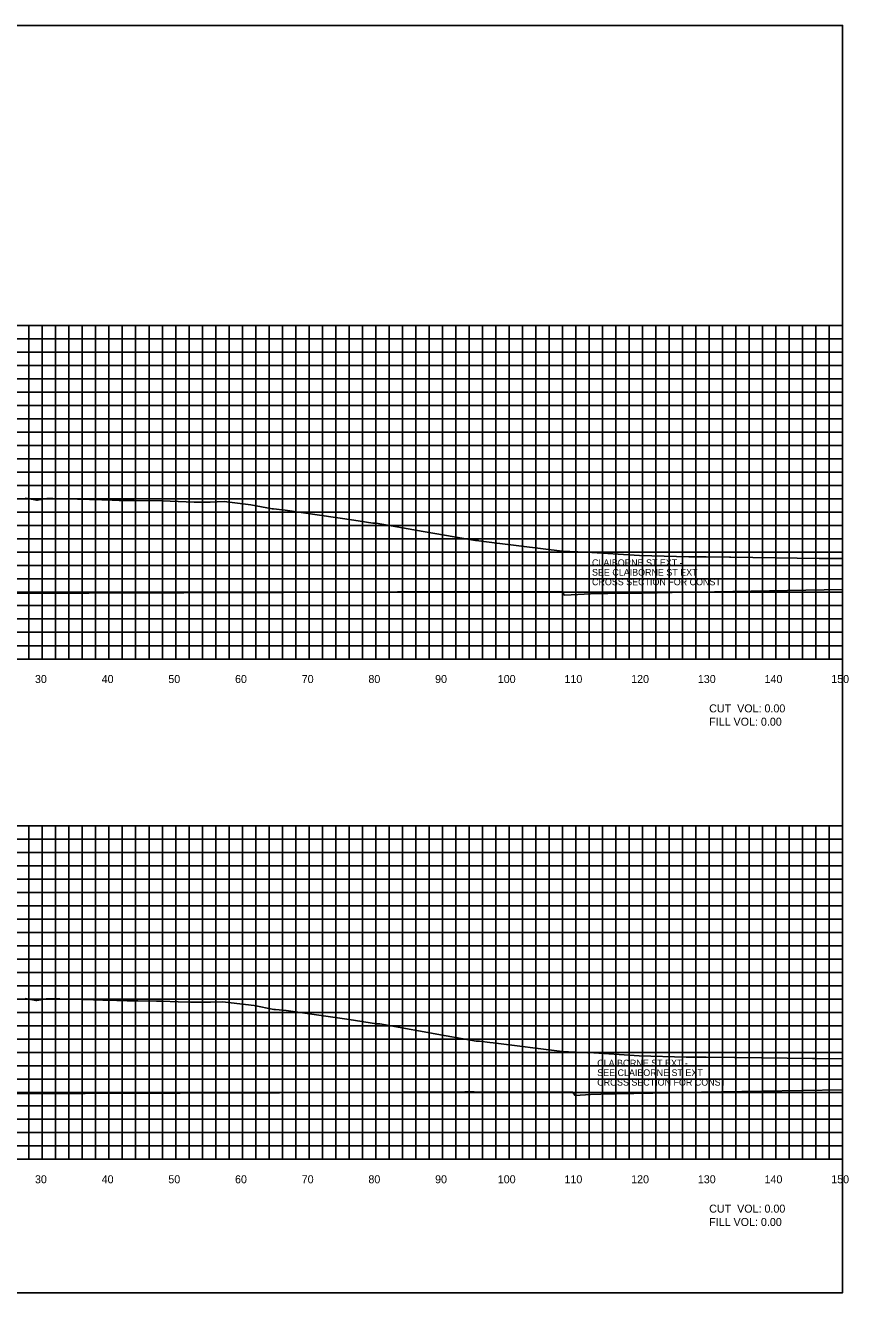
# Model space of a CAD drawing. Extents: x 1797305 to 1804485, y 245831 to 250849.
# Drawn here: x 1804018.5 to 1804141.9, y 250079.4 to 250269.4 of the extents above; entities that cross this region are included whole.
import ezdxf

# ---------------------------------------------------------------- set-up
doc = ezdxf.new("R2010")
doc.units = 0
for name, color, linetype in [('10', 7, 'Continuous'), ('29', 7, 'Continuous'), ('CL-CNST', 7, 'Continuous'), ('EDPV-LINE', 7, 'Continuous'), ('Level 31', 7, 'Continuous'), ('LIMT-CSLINE', 7, 'Continuous'), ('M-ROADS', 7, 'Continuous')]:
    doc.layers.add(name, color=color, linetype=linetype)

msp = doc.modelspace()

# ---------------------------------------------------------------- linework, layer by layer
msp.add_lwpolyline([(1803841, 250079.43), (1804141, 250079.43), (1804141, 250269.43), (1803841, 250269.43)], close=True)
at = {"layer": '29'}
for p, q in [((1803841, 250224.43), (1804141, 250224.43)), ((1804019, 250174.43), (1804019, 250224.43)), ((1804021, 250174.43), (1804021, 250224.43)), ((1804023, 250174.43), (1804023, 250224.43)), ((1804025, 250174.43), (1804025, 250224.43)), ((1804027, 250174.43), (1804027, 250224.43)), ((1804029, 250174.43), (1804029, 250224.43)), ((1804031, 250174.43), (1804031, 250224.43)), ((1804033, 250174.43), (1804033, 250224.43)), ((1804035, 250174.43), (1804035, 250224.43)), ((1804037, 250174.43), (1804037, 250224.43)), ((1804039, 250174.43), (1804039, 250224.43)), ((1804041, 250174.43), (1804041, 250224.43)), ((1804043, 250174.43), (1804043, 250224.43)), ((1804045, 250174.43), (1804045, 250224.43)), ((1804047, 250174.43), (1804047, 250224.43)), ((1804049, 250174.43), (1804049, 250224.43)), ((1804051, 250174.43), (1804051, 250224.43)), ((1804053, 250174.43), (1804053, 250224.43)), ((1804055, 250174.43), (1804055, 250224.43)), ((1804057, 250174.43), (1804057, 250224.43)), ((1804059, 250174.43), (1804059, 250224.43)), ((1804061, 250174.43), (1804061, 250224.43)), ((1804063, 250174.43), (1804063, 250224.43)), ((1804065, 250174.43), (1804065, 250224.43)), ((1804067, 250174.43), (1804067, 250224.43)), ((1804069, 250174.43), (1804069, 250224.43)), ((1804071, 250174.43), (1804071, 250224.43)), ((1804073, 250174.43), (1804073, 250224.43)), ((1804075, 250174.43), (1804075, 250224.43)), ((1804077, 250174.43), (1804077, 250224.43)), ((1804079, 250174.43), (1804079, 250224.43)), ((1804081, 250174.43), (1804081, 250224.43)), ((1804083, 250174.43), (1804083, 250224.43)), ((1804085, 250174.43), (1804085, 250224.43)), ((1804087, 250174.43), (1804087, 250224.43)), ((1804089, 250174.43), (1804089, 250224.43)), ((1804091, 250174.43), (1804091, 250224.43)), ((1804093, 250174.43), (1804093, 250224.43)), ((1804095, 250174.43), (1804095, 250224.43)), ((1804097, 250174.43), (1804097, 250224.43)), ((1804099, 250174.43), (1804099, 250224.43)), ((1804101, 250174.43), (1804101, 250224.43)), ((1804103, 250174.43), (1804103, 250224.43)), ((1804105, 250174.43), (1804105, 250224.43)), ((1804107, 250174.43), (1804107, 250224.43)), ((1804109, 250174.43), (1804109, 250224.43)), ((1804111, 250174.43), (1804111, 250224.43)), ((1804113, 250174.43), (1804113, 250224.43)), ((1804115, 250174.43), (1804115, 250224.43)), ((1804117, 250174.43), (1804117, 250224.43)), ((1804119, 250174.43), (1804119, 250224.43)), ((1804121, 250174.43), (1804121, 250224.43)), ((1804123, 250174.43), (1804123, 250224.43)), ((1804125, 250174.43), (1804125, 250224.43)), ((1804127, 250174.43), (1804127, 250224.43)), ((1804129, 250174.43), (1804129, 250224.43)), ((1804131, 250174.43), (1804131, 250224.43)), ((1804133, 250174.43), (1804133, 250224.43)), ((1804135, 250174.43), (1804135, 250224.43)), ((1804137, 250174.43), (1804137, 250224.43)), ((1804139, 250174.43), (1804139, 250224.43)), ((1804141, 250174.43), (1804141, 250224.43)), ((1803841, 250222.43), (1804141, 250222.43)), ((1803841, 250220.43), (1804141, 250220.43)), ((1803841, 250218.43), (1804141, 250218.43)), ((1803841, 250216.43), (1804141, 250216.43)), ((1803841, 250214.43), (1804141, 250214.43)), ((1803841, 250212.43), (1804141, 250212.43)), ((1803841, 250210.43), (1804141, 250210.43)), ((1803841, 250208.43), (1804141, 250208.43)), ((1803841, 250206.43), (1804141, 250206.43)), ((1803841, 250204.43), (1804141, 250204.43)), ((1803841, 250202.43), (1804141, 250202.43)), ((1803841, 250200.43), (1804141, 250200.43)), ((1803841, 250198.43), (1804141, 250198.43)), ((1803841, 250196.43), (1804141, 250196.43)), ((1803841, 250194.43), (1804141, 250194.43)), ((1803841, 250192.43), (1804141, 250192.43)), ((1803841, 250190.43), (1804141, 250190.43)), ((1803841, 250188.43), (1804141, 250188.43)), ((1803841, 250186.43), (1804141, 250186.43)), ((1803841, 250184.43), (1804141, 250184.43)), ((1803841, 250182.43), (1804141, 250182.43)), ((1803841, 250180.43), (1804141, 250180.43)), ((1803841, 250178.43), (1804141, 250178.43)), ((1803841, 250176.43), (1804141, 250176.43)), ((1803841, 250174.43), (1804141, 250174.43)), ((1803841, 250149.43), (1804141, 250149.43)), ((1804019, 250099.43), (1804019, 250149.43)), ((1804021, 250099.43), (1804021, 250149.43)), ((1804023, 250099.43), (1804023, 250149.43)), ((1804025, 250099.43), (1804025, 250149.43)), ((1804027, 250099.43), (1804027, 250149.43)), ((1804029, 250099.43), (1804029, 250149.43)), ((1804031, 250099.43), (1804031, 250149.43)), ((1804033, 250099.43), (1804033, 250149.43)), ((1804035, 250099.43), (1804035, 250149.43)), ((1804037, 250099.43), (1804037, 250149.43)), ((1804039, 250099.43), (1804039, 250149.43)), ((1804041, 250099.43), (1804041, 250149.43)), ((1804043, 250099.43), (1804043, 250149.43)), ((1804045, 250099.43), (1804045, 250149.43)), ((1804047, 250099.43), (1804047, 250149.43)), ((1804049, 250099.43), (1804049, 250149.43)), ((1804051, 250099.43), (1804051, 250149.43)), ((1804053, 250099.43), (1804053, 250149.43)), ((1804055, 250099.43), (1804055, 250149.43)), ((1804057, 250099.43), (1804057, 250149.43)), ((1804059, 250099.43), (1804059, 250149.43)), ((1804061, 250099.43), (1804061, 250149.43)), ((1804063, 250099.43), (1804063, 250149.43)), ((1804065, 250099.43), (1804065, 250149.43)), ((1804067, 250099.43), (1804067, 250149.43)), ((1804069, 250099.43), (1804069, 250149.43)), ((1804071, 250099.43), (1804071, 250149.43)), ((1804073, 250099.43), (1804073, 250149.43)), ((1804075, 250099.43), (1804075, 250149.43)), ((1804077, 250099.43), (1804077, 250149.43)), ((1804079, 250099.43), (1804079, 250149.43)), ((1804081, 250099.43), (1804081, 250149.43)), ((1804083, 250099.43), (1804083, 250149.43)), ((1804085, 250099.43), (1804085, 250149.43)), ((1804087, 250099.43), (1804087, 250149.43)), ((1804089, 250099.43), (1804089, 250149.43)), ((1804091, 250099.43), (1804091, 250149.43)), ((1804093, 250099.43), (1804093, 250149.43)), ((1804095, 250099.43), (1804095, 250149.43)), ((1804097, 250099.43), (1804097, 250149.43)), ((1804099, 250099.43), (1804099, 250149.43)), ((1804101, 250099.43), (1804101, 250149.43)), ((1804103, 250099.43), (1804103, 250149.43)), ((1804105, 250099.43), (1804105, 250149.43)), ((1804107, 250099.43), (1804107, 250149.43)), ((1804109, 250099.43), (1804109, 250149.43)), ((1804111, 250099.43), (1804111, 250149.43)), ((1804113, 250099.43), (1804113, 250149.43)), ((1804115, 250099.43), (1804115, 250149.43)), ((1804117, 250099.43), (1804117, 250149.43)), ((1804119, 250099.43), (1804119, 250149.43)), ((1804121, 250099.43), (1804121, 250149.43)), ((1804123, 250099.43), (1804123, 250149.43)), ((1804125, 250099.43), (1804125, 250149.43)), ((1804127, 250099.43), (1804127, 250149.43)), ((1804129, 250099.43), (1804129, 250149.43)), ((1804131, 250099.43), (1804131, 250149.43)), ((1804133, 250099.43), (1804133, 250149.43)), ((1804135, 250099.43), (1804135, 250149.43)), ((1804137, 250099.43), (1804137, 250149.43)), ((1804139, 250099.43), (1804139, 250149.43)), ((1804141, 250099.43), (1804141, 250149.43)), ((1803841, 250147.43), (1804141, 250147.43)), ((1803841, 250145.43), (1804141, 250145.43)), ((1803841, 250143.43), (1804141, 250143.43)), ((1803841, 250141.43), (1804141, 250141.43)), ((1803841, 250139.43), (1804141, 250139.43)), ((1803841, 250137.43), (1804141, 250137.43)), ((1803841, 250135.43), (1804141, 250135.43)), ((1803841, 250133.43), (1804141, 250133.43)), ((1803841, 250131.43), (1804141, 250131.43)), ((1803841, 250129.43), (1804141, 250129.43)), ((1803841, 250127.43), (1804141, 250127.43)), ((1803841, 250125.43), (1804141, 250125.43)), ((1803841, 250123.43), (1804141, 250123.43)), ((1803841, 250121.43), (1804141, 250121.43)), ((1803841, 250119.43), (1804141, 250119.43)), ((1803841, 250117.43), (1804141, 250117.43)), ((1803841, 250115.43), (1804141, 250115.43)), ((1803841, 250113.43), (1804141, 250113.43)), ((1803841, 250111.43), (1804141, 250111.43)), ((1803841, 250109.43), (1804141, 250109.43)), ((1803841, 250107.43), (1804141, 250107.43)), ((1803841, 250105.43), (1804141, 250105.43)), ((1803841, 250103.43), (1804141, 250103.43)), ((1803841, 250101.43), (1804141, 250101.43)), ((1803841, 250099.43), (1804141, 250099.43))]:
    msp.add_line(p, q, dxfattribs=at)
at = {"layer": 'CL-CNST'}
for points in [[(1803998.84, 250184.22), (1804026.58, 250184.29), (1804027.99, 250184.28), (1804056.54, 250184.4), (1804057.15, 250184.4), (1804082.8, 250184.53), (1804083.02, 250184.52), (1804084.74, 250184.5), (1804086.31, 250184.5), (1804094.51, 250184.49), (1804098.34, 250184.49), (1804098.34, 250184.49), (1804098.35, 250184.49), (1804098.72, 250184.49), (1804098.99, 250184.49), (1804099.13, 250184.27), (1804099.31, 250184), (1804101.31, 250184.09), (1804103.2, 250184.18), (1804105.78, 250184.23), (1804110.97, 250184.32), (1804115.47, 250184.41), (1804119.03, 250184.47), (1804141, 250184.87)], [(1803998.27, 250109.22), (1804025.96, 250109.29), (1804027.43, 250109.29), (1804055.92, 250109.4), (1804056.59, 250109.41), (1804084.36, 250109.54), (1804084.45, 250109.54), (1804085.75, 250109.52), (1804086.3, 250109.51), (1804095.4, 250109.51), (1804099.9, 250109.5), (1804099.91, 250109.5), (1804099.91, 250109.5), (1804100.23, 250109.51), (1804100.55, 250109.51), (1804100.72, 250109.25), (1804100.88, 250109.01), (1804103.2, 250109.12), (1804104.76, 250109.2), (1804106.9, 250109.24), (1804112.53, 250109.34), (1804114.91, 250109.38), (1804116.78, 250109.42), (1804141, 250109.86)]]:
    msp.add_lwpolyline(points, dxfattribs=at)
at = {"layer": 'Level 31'}
for p, q in [((1804141, 250174.43), (1804141, 250224.43)), ((1804141.06, 250224.43), (1804141, 250224.43)), ((1804141.06, 250214.43), (1804141, 250214.43)), ((1804141.06, 250204.43), (1804141, 250204.43)), ((1804141.06, 250194.43), (1804141, 250194.43)), ((1804141.06, 250184.43), (1804141, 250184.43)), ((1803841, 250174.43), (1804141, 250174.43)), ((1804021, 250174.37), (1804021, 250174.43)), ((1804031, 250174.37), (1804031, 250174.43)), ((1804041, 250174.37), (1804041, 250174.43)), ((1804051, 250174.37), (1804051, 250174.43)), ((1804061, 250174.37), (1804061, 250174.43)), ((1804071, 250174.37), (1804071, 250174.43)), ((1804081, 250174.37), (1804081, 250174.43)), ((1804091, 250174.37), (1804091, 250174.43)), ((1804101, 250174.37), (1804101, 250174.43)), ((1804111, 250174.37), (1804111, 250174.43)), ((1804121, 250174.37), (1804121, 250174.43)), ((1804131, 250174.37), (1804131, 250174.43)), ((1804141, 250174.37), (1804141, 250174.43)), ((1804141.06, 250174.43), (1804141, 250174.43)), ((1804141, 250099.43), (1804141, 250149.43)), ((1804141.06, 250149.43), (1804141, 250149.43)), ((1804141.06, 250139.43), (1804141, 250139.43)), ((1804141.06, 250129.43), (1804141, 250129.43)), ((1804141.06, 250119.43), (1804141, 250119.43)), ((1804141.06, 250109.43), (1804141, 250109.43)), ((1803841, 250099.43), (1804141, 250099.43)), ((1804021, 250099.37), (1804021, 250099.43)), ((1804031, 250099.37), (1804031, 250099.43)), ((1804041, 250099.37), (1804041, 250099.43)), ((1804051, 250099.37), (1804051, 250099.43)), ((1804061, 250099.37), (1804061, 250099.43)), ((1804071, 250099.37), (1804071, 250099.43)), ((1804081, 250099.37), (1804081, 250099.43)), ((1804091, 250099.37), (1804091, 250099.43)), ((1804101, 250099.37), (1804101, 250099.43)), ((1804111, 250099.37), (1804111, 250099.43)), ((1804121, 250099.37), (1804121, 250099.43)), ((1804131, 250099.37), (1804131, 250099.43)), ((1804141, 250099.37), (1804141, 250099.43)), ((1804141.06, 250099.43), (1804141, 250099.43))]:
    msp.add_line(p, q, dxfattribs=at)
at = {"layer": 'M-ROADS'}
for points in [[(1804018.42, 250198.54), (1804018.63, 250198.51), (1804018.63, 250198.51), (1804018.7, 250198.5), (1804018.73, 250198.49), (1804018.76, 250198.49), (1804020.17, 250198.24), (1804020.18, 250198.24), (1804020.24, 250198.24), (1804021.7, 250198.5), (1804022.37, 250198.5), (1804022.4, 250198.5), (1804022.43, 250198.5), (1804022.46, 250198.5), (1804022.5, 250198.5), (1804022.54, 250198.5), (1804022.57, 250198.5), (1804029.93, 250198.28), (1804031.48, 250198.23), (1804031.91, 250198.22), (1804032.55, 250198.2), (1804033.02, 250198.19), (1804033.15, 250198.19), (1804033.63, 250198.19), (1804033.89, 250198.19), (1804034.79, 250198.18), (1804039.04, 250198.14), (1804040.19, 250198.1), (1804043.77, 250197.96), (1804044.37, 250197.96), (1804046.18, 250197.95), (1804048.26, 250198.03), (1804052.27, 250197.54), (1804055.48, 250196.93), (1804055.68, 250196.93), (1804057.44, 250196.74), (1804067.69, 250195.27), (1804070.56, 250194.81), (1804070.98, 250194.81), (1804071.08, 250194.81), (1804078.12, 250193.54), (1804085.98, 250192.18), (1804086.39, 250192.18), (1804086.44, 250192.17), (1804089.17, 250191.82), (1804089.63, 250191.77), (1804098.96, 250190.61), (1804102.46, 250190.44), (1804102.62, 250190.45), (1804110.53, 250189.95), (1804117.95, 250189.76), (1804118.14, 250189.76), (1804120.07, 250189.73), (1804120.23, 250189.73), (1804120.57, 250189.73), (1804124.05, 250189.69), (1804124.25, 250189.69), (1804137.51, 250189.51), (1804137.87, 250189.51), (1804138.08, 250189.5), (1804141, 250189.48)], [(1804018.45, 250123.52), (1804018.61, 250123.5), (1804018.66, 250123.48), (1804018.73, 250123.48), (1804020.04, 250123.24), (1804020.05, 250123.24), (1804020.2, 250123.25), (1804021.61, 250123.5), (1804022.25, 250123.5), (1804022.28, 250123.5), (1804022.31, 250123.5), (1804022.34, 250123.5), (1804022.38, 250123.5), (1804022.42, 250123.5), (1804022.47, 250123.5), (1804023.63, 250123.47), (1804028.68, 250123.31), (1804030.09, 250123.27), (1804032.16, 250123.21), (1804033.72, 250123.18), (1804034.13, 250123.18), (1804034.52, 250123.18), (1804035.33, 250123.17), (1804038.14, 250123.15), (1804038.94, 250123.14), (1804041.39, 250123.05), (1804043.21, 250122.98), (1804044.65, 250122.97), (1804046.22, 250122.97), (1804048.03, 250123.04), (1804052.77, 250122.46), (1804055.72, 250121.89), (1804055.95, 250121.89), (1804057.57, 250121.72), (1804067.02, 250120.36), (1804071.1, 250119.72), (1804071.48, 250119.72), (1804071.61, 250119.72), (1804081.58, 250117.92), (1804086.07, 250117.14), (1804086.52, 250117.14), (1804086.55, 250117.14), (1804088.1, 250116.94), (1804088.61, 250116.88), (1804098.94, 250115.6), (1804102.81, 250115.41), (1804102.97, 250115.42), (1804110.48, 250114.94), (1804117.53, 250114.76), (1804117.72, 250114.76), (1804120.07, 250114.73), (1804120.27, 250114.73), (1804120.57, 250114.73), (1804124.81, 250114.68), (1804125.06, 250114.68), (1804136.49, 250114.53), (1804136.8, 250114.52), (1804137.06, 250114.52), (1804141, 250114.49)]]:
    msp.add_lwpolyline(points, dxfattribs=at)

# ---------------------------------------------------------------- texts
at = {"layer": '10'}
for s, p in [('30', (1804019.9, 250170.83)), ('40', (1804029.9, 250170.83)), ('50', (1804039.9, 250170.83)), ('60', (1804049.9, 250170.83)), ('70', (1804059.9, 250170.83)), ('80', (1804069.9, 250170.83)), ('90', (1804079.9, 250170.83)), ('100', (1804089.3, 250170.83)), ('110', (1804099.3, 250170.83)), ('120', (1804109.3, 250170.83)), ('130', (1804119.3, 250170.83)), ('140', (1804129.3, 250170.83)), ('150', (1804139.3, 250170.83)), ('30', (1804019.9, 250095.83)), ('40', (1804029.9, 250095.83)), ('50', (1804039.9, 250095.83)), ('60', (1804049.9, 250095.83)), ('70', (1804059.9, 250095.83)), ('80', (1804069.9, 250095.83)), ('90', (1804079.9, 250095.83)), ('100', (1804089.3, 250095.83)), ('110', (1804099.3, 250095.83)), ('120', (1804109.3, 250095.83)), ('130', (1804119.3, 250095.83)), ('140', (1804129.3, 250095.83)), ('150', (1804139.3, 250095.83))]:
    msp.add_text(s, height=1.2, dxfattribs=at).set_placement(p)
at = {"layer": 'EDPV-LINE'}
for s, p in [('CUT  VOL: 0.00', (1804121, 250166.43)), ('FILL VOL: 0.00', (1804121, 250164.43)), ('CUT  VOL: 0.00', (1804121, 250091.43)), ('FILL VOL: 0.00', (1804121, 250089.43))]:
    msp.add_text(s, height=1.2, dxfattribs=at).set_placement(p)
at = {"layer": 'LIMT-CSLINE'}
for s, p in [('CLAIBORNE ST EXT -', (1804103.43, 250188.37)), ('SEE CLAIBORNE ST EXT', (1804103.43, 250186.93)), ('CROSS SECTION FOR CONST ', (1804103.43, 250185.49)), ('CLAIBORNE ST EXT -', (1804104.21, 250113.35)), ('SEE CLAIBORNE ST EXT', (1804104.21, 250111.91)), ('CROSS SECTION FOR CONST ', (1804104.21, 250110.47))]:
    msp.add_text(s, height=1, dxfattribs=at).set_placement(p)

doc.saveas('drawing.dxf')
